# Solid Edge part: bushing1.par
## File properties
Title: Bushing
Author: Abhinav Rai
Template: normal.par
Last saved by: Cadcim
Revision: 4
Application: Solid Edge
Density: 0.28179277014 lbm/in^3
Accuracy: 0.01
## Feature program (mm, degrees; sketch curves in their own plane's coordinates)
sketch for "unnamed RevolvedProtrusion 1" plane through (0, 0, -8.3976) normal (0, 0, 1) x-axis (1, 0, 0)
  line (-23.1281, 31.75) -> (-23.1281, 34.9556)
  line (-23.1281, 34.9556) -> (-38.3879, 34.9556)
  line (-38.3879, 34.9556) -> (-38.3879, 31.75)
  line (-38.3879, 31.75) -> (-23.1281, 31.75)
revolve "unnamed RevolvedProtrusion 1" add full turn 360 deg about sketch line (-48.5775, 25.4) -> (54.7954, 25.4)
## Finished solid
Body 1: solid body, 4 faces, 4 edges, 0 vertices.
  Faces by surface: cylinder 2, plane 2
  Edges by curve: circle 4
Bounding box of the edges (mm): 15.260 x 19.111 x 19.111, from (-38.3879, 15.8444, -17.9532) to (-23.1281, 34.9556, 1.1579).
Cylindrical faces by radius (mm): R6.35 x1, R9.5556 x1
Planar faces by outward normal: +x 1, -x 1
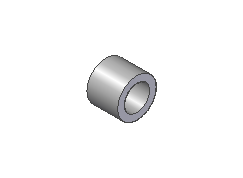
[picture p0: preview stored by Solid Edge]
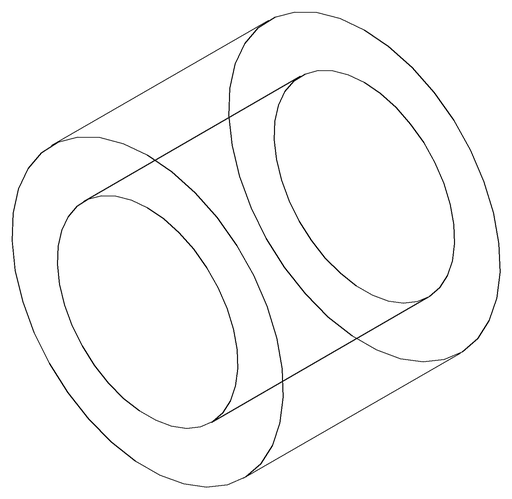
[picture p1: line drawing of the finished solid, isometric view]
